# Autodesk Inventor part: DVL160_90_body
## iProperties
Created: 2009-09
Part Number: DVL160_90_body
Document SubType Name: Modeling
Designer: TB
Mass: 4139.28 g
Surface Area: 4486.14 cm^2
Volume: 4139.28 cm^3
Density: 1 g/cm^3
Author: TB
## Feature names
1. Kropp [Revolution]
2. Chamfer
3. Extrusion2
4. Hole1
5. Revolution2
6. Hole2
7. Fillet1
